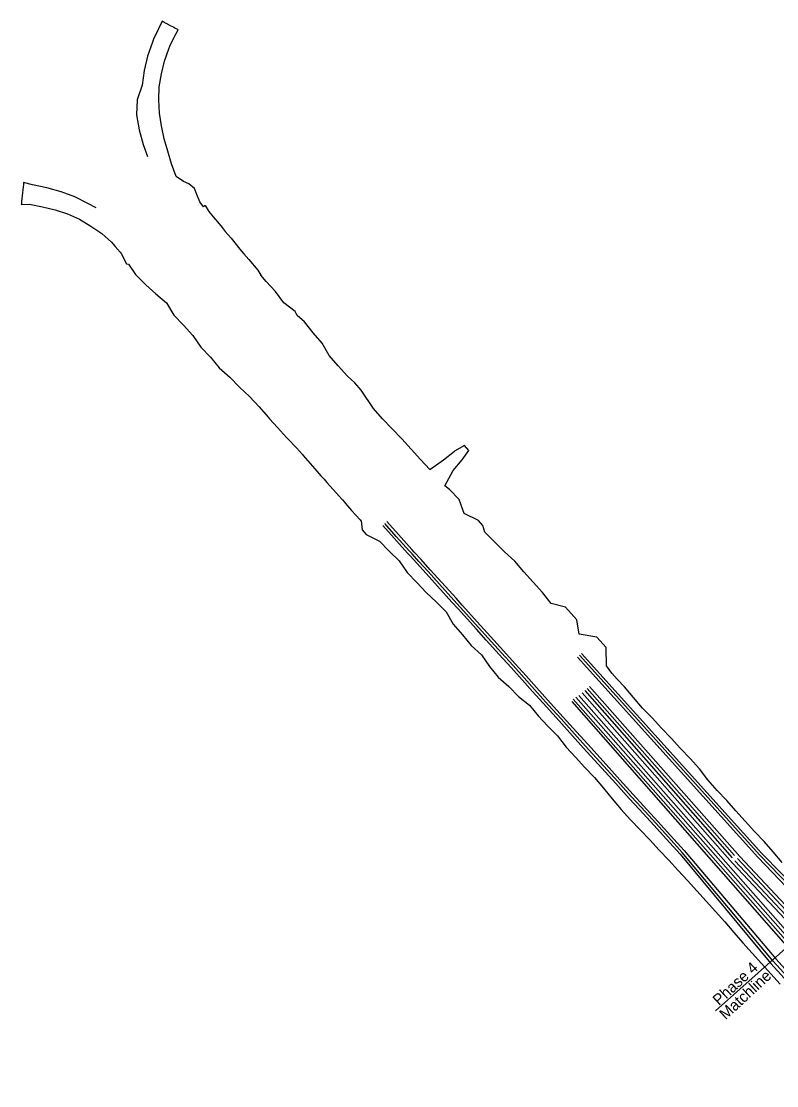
# Model space of a CAD drawing. Extents: x -5665 to 1997148, y 4 to 812485.
# Drawn here: x 1957360 to 1960081, y 808654 to 812485 of the extents above; entities that cross this region are included whole.
import ezdxf

# ---------------------------------------------------------------- set-up
doc = ezdxf.new("R2010")
doc.units = 0
for name, color, linetype in [('RD_EX_Road', 7, 'Continuous'), ('RD_PD_ALT1_TrvlWay', 7, 'Continuous'), ('RD_PD_CstnLmt', 7, 'Continuous'), ('RD_PD_Final_LnLine', 7, 'Continuous'), ('RD_SHT_MatchLine', 7, 'Continuous')]:
    doc.layers.add(name, color=color, linetype=linetype)

msp = doc.modelspace()

# ---------------------------------------------------------------- linework, layer by layer
at = {"layer": 'RD_EX_Road'}
for p, q in [((1960012.6, 809476.7), (1959362.7, 810196.2)), ((1960019.9, 809483.3), (1959370, 810202.8)), ((1960027.2, 809489.9), (1959377.3, 810209.3)), ((1959380.5, 810067.7), (1959921.2, 809454.9)), ((1959389.6, 810075.5), (1959920.4, 809473.9)), ((1959398.5, 810083.6), (1959928.8, 809482.5)), ((1959406.6, 810091), (1959947.3, 809478.2)), ((1959342.9, 810036.2), (1960121.4, 809150.3)), ((1959347.8, 810045.2), (1960130.3, 809158.3)), ((1959357.7, 810052.1), (1960139.2, 809166.4)), ((1959368.1, 810058.5), (1960148.1, 809174.4)), ((1959732.8, 809486.4), (1960059.1, 809093.9)), ((1960068, 809102), (1959740.2, 809493.2)), ((1959747.7, 809499.9), (1960076.9, 809110)), ((1960027.2, 809489.9), (1960247.5, 809264.3)), ((1960167.4, 809191.9), (1959921.3, 809454.7)), ((1959930.2, 809462.8), (1960176.3, 809199.9)), ((1959939.1, 809470.8), (1960185.2, 809208)), ((1960194.1, 809216), (1959947.3, 809478.2)), ((1960012.6, 809476.7), (1960229.7, 809248.2)), ((1960238.6, 809256.3), (1960019.9, 809483.3))]:
    msp.add_line(p, q, dxfattribs=at)
for points in [[(1959740.2, 809493.2), (1959740, 809493.5), (1959690.8, 809547.6), (1959645, 809598), (1959593.3, 809654.4), (1959556.6, 809694.6), (1959508.2, 809748.2), (1959469.9, 809790.5), (1959392.6, 809875.8), (1959352.7, 809920), (1959304.4, 809973.7), (1959259.1, 810023.8), (1959208.6, 810079.6), (1959170.9, 810121.6), (1959131.4, 810165.5), (1959089.1, 810212.1), (1959042, 810264.2), (1959006.6, 810303.2), (1958940.7, 810376.6), (1958918.3, 810401.4), (1958866.8, 810458.3), (1958825.7, 810504), (1958792.2, 810540.8), (1958767.6, 810567.5), (1958767.6, 810567.5), (1958758.6, 810577.2), (1958710.7, 810630.6), (1958669.3, 810677.2)], [(1959747.7, 809499.9), (1959747.4, 809500.2), (1959698.3, 809554.3), (1959652.4, 809604.7), (1959600.8, 809661.1), (1959564, 809701.4), (1959515.6, 809754.9), (1959477.4, 809797.3), (1959400.1, 809882.5), (1959360.2, 809926.8), (1959311.9, 809980.4), (1959266.5, 810030.6), (1959216.1, 810086.3), (1959178.3, 810128.4), (1959138.9, 810172.2), (1959096.6, 810218.9), (1959049.4, 810270.9), (1959014.1, 810309.9), (1958948.2, 810383.4), (1958925.7, 810408.1), (1958874.3, 810465.1), (1958833.1, 810510.8), (1958799.7, 810547.6), (1958775, 810574.2), (1958775, 810574.2), (1958766.1, 810583.9), (1958718.2, 810637.4), (1958676.8, 810683.9)], [(1959732.8, 809486.4), (1959732.5, 809486.7), (1959683.4, 809540.8), (1959637.5, 809591.2), (1959585.9, 809647.6), (1959549.1, 809687.9), (1959500.7, 809741.4), (1959462.5, 809783.8), (1959385.2, 809869), (1959345.3, 809913.3), (1959296.9, 809966.9), (1959251.6, 810017.1), (1959201.2, 810072.8), (1959163.4, 810114.9), (1959124, 810158.7), (1959081.7, 810205.4), (1959034.5, 810257.4), (1958999.2, 810296.4), (1958933.2, 810369.9), (1958910.8, 810394.6), (1958859.4, 810451.6), (1958818.2, 810497.3), (1958784.8, 810534.1), (1958760.1, 810560.7), (1958760.1, 810560.7), (1958751.1, 810570.4), (1958703.3, 810623.9), (1958661.9, 810670.4)]]:
    msp.add_lwpolyline(points, dxfattribs=at)
at = {"layer": 'RD_PD_ALT1_TrvlWay'}
for p, q in [((1960076.9, 809110), (1960475.2, 808669.7)), ((1960059.1, 809093.9), (1960457.4, 808653.6))]:
    msp.add_line(p, q, dxfattribs=at)
at = {"layer": 'RD_PD_CstnLmt'}
for p, q in [((1958955.8, 810957.7), (1958920.3, 810937.4)), ((1958971.7, 810939.8), (1958955.8, 810957.7)), ((1958831.9, 810871.4), (1958881, 810906.3)), ((1958881, 810906.3), (1958920.3, 810937.4)), ((1958915.3, 810867.9), (1958948, 810906.3)), ((1958948, 810906.3), (1958971.7, 810939.8)), ((1958885, 810813), (1958915.3, 810867.9)), ((1958587.3, 810653.9), (1958602, 810637.6)), ((1958602, 810637.6), (1958650.5, 810613.5)), ((1958650.5, 810613.5), (1958684.9, 810577.2)), ((1958721.4, 810542.9), (1958750.1, 810501.4)), ((1958750.1, 810501.4), (1958784.2, 810464.8)), ((1958784.2, 810464.8), (1958818.8, 810428.7)), ((1958818.8, 810428.7), (1958855.5, 810394.5)), ((1958855.5, 810394.5), (1958890.5, 810358.7)), ((1958890.5, 810358.7), (1958916, 810314.4)), ((1958916, 810314.4), (1958949.3, 810277)), ((1958949.3, 810277), (1958980.8, 810238.2)), ((1958980.8, 810238.2), (1959017.8, 810204.2)), ((1959017.8, 810204.2), (1959046.4, 810162.6)), ((1959046.4, 810162.6), (1959077.8, 810123.6)), ((1959077.8, 810123.6), (1959115.9, 810090.7)), ((1959115.9, 810090.7), (1959150.7, 810054.7)), ((1959150.7, 810054.7), (1959190.7, 810023.5)), ((1959190.7, 810023.5), (1959222.1, 809984.4))]:
    msp.add_line(p, q, dxfattribs=at)
for points in [[(1958022.6, 811821.4), (1958016.9, 811816.8), (1958002.8, 811835.6), (1957992.5, 811861.4), (1957983.8, 811882.5), (1957983.8, 811882.5), (1957964.1, 811900), (1957944.3, 811908.8), (1957918.4, 811926), (1957901.8, 811971.6), (1957888.4, 812017.3), (1957874.7, 812062.3), (1957864.9, 812108.2), (1957857.9, 812154.7), (1957855.2, 812201.7), (1957857.3, 812248.8), (1957864.6, 812295.3), (1957875.5, 812341.2), (1957891.4, 812385.6), (1957895.5, 812395.6), (1957911.1, 812428.3), (1957924.7, 812454.5), (1957923.9, 812454.9), (1957913.3, 812460.6), (1957909.8, 812462.5), (1957908, 812463.4), (1957897.4, 812469.1), (1957886.8, 812474.7), (1957885.1, 812475.7), (1957881.6, 812477.5), (1957871, 812483.2), (1957867.8, 812484.9), (1957854.3, 812457.4), (1957836.8, 812420.6), (1957832.3, 812409.2), (1957815.2, 812359), (1957802.5, 812307.6), (1957795.8, 812255.1), (1957777.7, 812202.4), (1957775.6, 812147.9), (1957784.9, 812094.1), (1957799.5, 812041.7), (1957814.3, 811997.9)], [(1957629.6, 811813.4), (1957600, 811829.6), (1957552.6, 811852.5), (1957503.3, 811871), (1957452.7, 811885.9), (1957401.1, 811896.6), (1957368.2, 811904.2), (1957367.7, 811899), (1957366.5, 811887), (1957365.9, 811881.1), (1957365.7, 811879.1), (1957364.5, 811867.1), (1957361.3, 811835.8), (1957361.1, 811833.8), (1957360.5, 811827.8), (1957360.3, 811825.9), (1957360.3, 811825.9), (1957390.3, 811827), (1957436.3, 811817.4), (1957482.1, 811806.5), (1957527, 811791.9), (1957570.3, 811772.6), (1957610.6, 811747.7), (1957649.9, 811721.6), (1957684.6, 811689.4), (1957698.7, 811674.4), (1957715.8, 811654.2), (1957719.8, 811649.1), (1957739.3, 811611.9), (1957745.8, 811610.5), (1957772.1, 811573.9), (1957807.2, 811537.9), (1957808.5, 811536.6), (1957845.1, 811504.3), (1957883.5, 811471.2), (1957909.5, 811427.3), (1957944, 811390.8), (1957978, 811353.9), (1958007, 811312.5), (1958041.1, 811275.9), (1958072.6, 811237), (1958111.2, 811204.5), (1958145.9, 811168.4), (1958182.4, 811134), (1958216.5, 811097.5), (1958249.1, 811059.5), (1958254, 811053.7), (1958282.8, 811022.6), (1958315.5, 810987.3), (1958316.8, 810985.9), (1958318.8, 810983.7), (1958350.8, 810949.3), (1958372.6, 810925.7), (1958375.7, 810922.1), (1958384.3, 810912.2), (1958417, 810874.3), (1958439.2, 810849.3), (1958450.4, 810837.1), (1958460.8, 810824.8), (1958483.2, 810799.4), (1958516.6, 810762.1), (1958524.9, 810752.6), (1958528, 810748.9), (1958549.4, 810724.4), (1958580.7, 810689.9), (1958583, 810687.4), (1958583.9, 810686.4), (1958587.3, 810653.9)], [(1958022.6, 811821.4), (1958036, 811800.1), (1958051.8, 811780.7), (1958066.5, 811763), (1958083.6, 811742.1), (1958095, 811728.3), (1958116.2, 811704.2), (1958147.5, 811665.2), (1958162.2, 811647.6), (1958180, 811627.2), (1958212.4, 811589.1), (1958222.3, 811571.1)], [(1958831.9, 810871.4), (1958797.9, 810908), (1958764.1, 810944.9), (1958730.6, 810982.1), (1958696.3, 811018.5), (1958661.3, 811054.1), (1958628.3, 811091.2), (1958584.5, 811157.5), (1958561.7, 811184.1), (1958534.7, 811207.3), (1958501.5, 811244.2), (1958469.3, 811282.4), (1958443.3, 811325.9), (1958410.8, 811363.9), (1958379.8, 811403.1), (1958353.3, 811426.4), (1958346.5, 811440.4), (1958305.8, 811471.7), (1958276.2, 811512.1), (1958241.9, 811548.6), (1958222.3, 811571.1)], [(1959361.2, 810330.5), (1959319.6, 810376.4), (1959268, 810389.4), (1959236.8, 810428.6), (1959204, 810466.4), (1959169.7, 810502.8), (1959137.5, 810541.1), (1959100.7, 810575.1), (1959065.2, 810610.4), (1959029.6, 810645.7), (1959022.7, 810670.5), (1959006.5, 810688.3), (1958955.2, 810713.2), (1958936.9, 810764.1), (1958901.7, 810799.7), (1958885, 810813)], [(1958684.9, 810577.2), (1958721.4, 810542.9)], [(1960100.7, 809457.1), (1960067.9, 809494.8), (1960035.4, 809532.9), (1960000.7, 809568.9), (1959966.4, 809605.3), (1959933.4, 809642.9), (1959900.4, 809680.5), (1959866, 809716.7), (1959832.7, 809754.1), (1959802.2, 809793.8), (1959769, 809831.3), (1959734.6, 809867.6), (1959700.8, 809904.4), (1959665.7, 809940.1), (1959632.4, 809977.4), (1959597.1, 810012.9), (1959564.4, 810050.7), (1959531.9, 810088.7), (1959505.5, 810117.3), (1959486.8, 810138), (1959467.3, 810165.2), (1959465.9, 810231.3), (1959432.3, 810268.4), (1959368.9, 810278.4), (1959361.2, 810330.5)], [(1959222.1, 809984.4), (1959256.3, 809947.9), (1959291.6, 809912.5), (1959321.8, 809872.4), (1959356.4, 809836.3), (1959390.1, 809799.3), (1959424.6, 809763.1), (1959456.8, 809724.8), (1959488.4, 809686), (1959520.4, 809647.5), (1959553.9, 809610.4), (1959588.8, 809574.5), (1959623.4, 809538.4), (1959657.3, 809501.7), (1959691.9, 809465.5), (1959725.5, 809428.5), (1959759.4, 809391.7), (1959793.4, 809355.1), (1959826.2, 809317.3), (1959859.9, 809280.4), (1959893.7, 809243.5), (1959926.2, 809205.5), (1959958.6, 809167.4), (1959992.5, 809130.6), (1960025.7, 809093.3), (1960058.8, 809055.8), (1960092.9, 809019.2)]]:
    msp.add_lwpolyline(points, dxfattribs=at)
at = {"layer": 'RD_PD_Final_LnLine'}
msp.add_line((1960068, 809102), (1960466.3, 808661.6), dxfattribs=at)
at = {"layer": 'RD_SHT_MatchLine'}
msp.add_line((1960298.3, 809312.8), (1959859.6, 808923.5), dxfattribs=at)

# ---------------------------------------------------------------- texts
for s, p in [('Phase 4 ', (1959872.6, 808939.9)), ('Matchline', (1959896.8, 808888.7))]:
    msp.add_text(s, height=40, rotation=42.7846, dxfattribs=at).set_placement(p)

doc.saveas('drawing.dxf')
